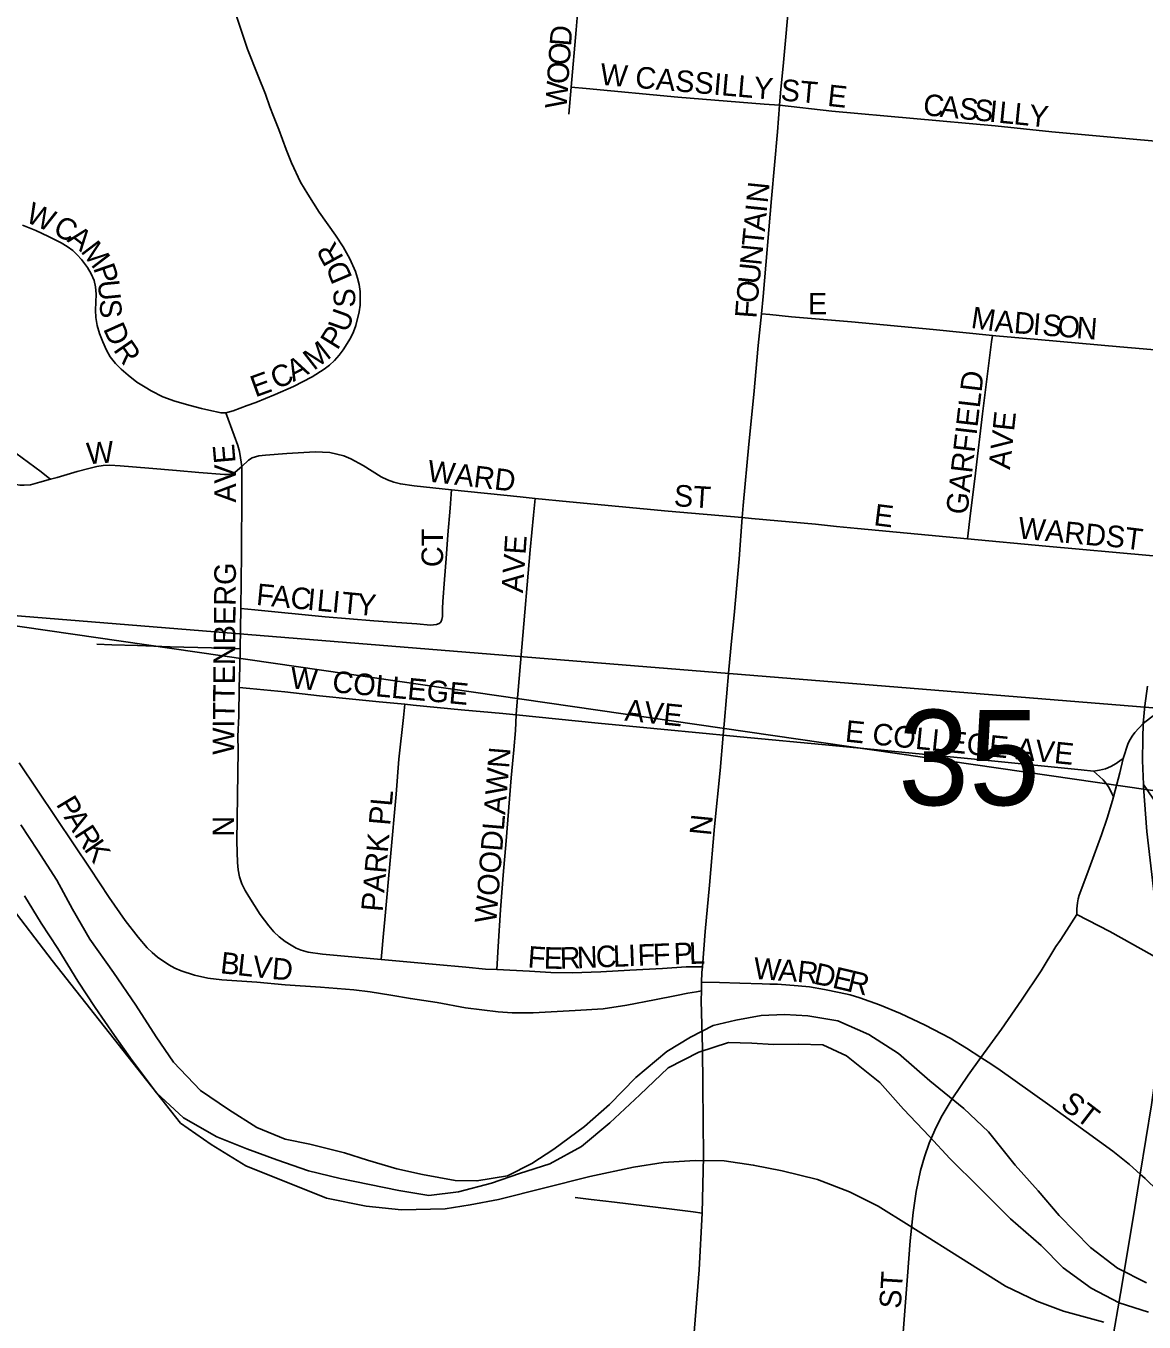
# Model space of a CAD drawing. Extents: x -209 to 4852, y 0 to 905.
# Drawn here: x 111.69 to 121.5, y 279.25 to 290.63 of the extents above; entities that cross this region are included whole.
import ezdxf

# ---------------------------------------------------------------- set-up
doc = ezdxf.new("R2010")
doc.units = 0
for name, color, linetype in [('GM_X_Airport_Location_Class_2', 7, 'Continuous'), ('GM_X_Airport_Location_Class_3', 7, 'Continuous'), ('GM_X_County_Subdivision_Text', 7, 'Continuous'), ('GM_X_Major_Lake', 7, 'Continuous'), ('GM_X_Rail_Line', 7, 'Continuous'), ('GM_X_Township_Road_Text', 7, 'Continuous'), ('GM_X_US_Route', 7, 'Continuous'), ('SH_Text', 7, 'Continuous')]:
    doc.layers.add(name, color=color, linetype=linetype)

msp = doc.modelspace()

# ---------------------------------------------------------------- linework, layer by layer
at = {"layer": 'GM_X_Airport_Location_Class_2'}
for points in [[(116.475, 290.093), (116.519, 290.597), (116.538, 290.842), (116.594, 291.457), (116.623, 291.758)], [(118.303, 289.934), (118.311, 290.043), (118.336, 290.308), (118.391, 290.894), (118.434, 291.377), (118.453, 291.587)], [(113.908, 289.721), (113.862, 289.837), (113.829, 289.921), (113.792, 290.03), (113.724, 290.198), (113.635, 290.426), (113.554, 290.662), (113.497, 290.841), (113.479, 290.901), (113.466, 290.961), (113.459, 291.023), (113.461, 291.086), (113.469, 291.147), (113.483, 291.207), (113.503, 291.265), (113.555, 291.401)], [(116.454, 289.856), (116.475, 290.093)], [(116.475, 290.093), (116.605, 290.081), (117.41, 290.004), (118.168, 289.944), (118.303, 289.934)], [(118.143, 288.103), (118.158, 288.254), (118.233, 289.116), (118.285, 289.702), (118.303, 289.934)], [(118.303, 289.934), (118.761, 289.883), (120.194, 289.752), (120.692, 289.702), (121.437, 289.634), (121.735, 289.606), (121.982, 289.582), (122.096, 289.57)], [(113.444, 287.233), (113.509, 287.252), (113.569, 287.274), (113.631, 287.297), (113.708, 287.325), (113.877, 287.394), (114.038, 287.466), (114.202, 287.55), (114.305, 287.616), (114.353, 287.653), (114.397, 287.694), (114.437, 287.739), (114.473, 287.787), (114.537, 287.89), (114.564, 287.944), (114.585, 288.001), (114.614, 288.119), (114.621, 288.178), (114.623, 288.239), (114.621, 288.299), (114.614, 288.359), (114.6, 288.417), (114.58, 288.474), (114.531, 288.585), (114.473, 288.692), (114.406, 288.793), (114.262, 288.994), (114.162, 289.152), (114.1, 289.26), (114.02, 289.429), (113.974, 289.545), (113.908, 289.721)], [(113.444, 287.233), (113.401, 287.234), (113.375, 287.239), (113.322, 287.25), (113.229, 287.272), (113.131, 287.298), (112.996, 287.336), (112.89, 287.375), (112.789, 287.426), (112.735, 287.459), (112.664, 287.503), (112.586, 287.565), (112.524, 287.617), (112.475, 287.666), (112.43, 287.725), (112.396, 287.784), (112.363, 287.856), (112.335, 287.931), (112.314, 288), (112.303, 288.072), (112.301, 288.135), (112.303, 288.206), (112.306, 288.274), (112.301, 288.339), (112.287, 288.395), (112.262, 288.454), (112.23, 288.51), (112.178, 288.581), (112.139, 288.622), (112.1, 288.66), (112.052, 288.695), (111.998, 288.726), (111.888, 288.783), (111.775, 288.834), (111.717, 288.859), (111.659, 288.881)], [(117.974, 286.314), (117.982, 286.42), (118.034, 286.958), (118.078, 287.396), (118.116, 287.825), (118.143, 288.103)], [(118.143, 288.103), (118.217, 288.096), (118.408, 288.077), (118.935, 288.033), (119.65, 287.965), (120.17, 287.913)], [(119.953, 286.127), (119.959, 286.176), (119.973, 286.302), (120.023, 286.705), (120.084, 287.225), (120.162, 287.856), (120.17, 287.913)], [(120.17, 287.913), (120.199, 287.91), (120.569, 287.877), (121.288, 287.814), (121.662, 287.781), (121.839, 287.759), (121.921, 287.742)], [(113.584, 286.763), (113.573, 286.839), (113.563, 286.893), (113.549, 286.946), (113.517, 287.036), (113.444, 287.233)], [(110.972, 286.988), (111.28, 286.787), (111.384, 286.718), (111.547, 286.626), (111.605, 286.604), (111.636, 286.599), (111.674, 286.598), (111.73, 286.603), (111.811, 286.624), (111.906, 286.65)], [(111.601, 286.88), (111.711, 286.797), (111.822, 286.717), (111.885, 286.667), (111.906, 286.65)], [(113.584, 286.763), (113.643, 286.819), (113.676, 286.84), (113.732, 286.855), (113.791, 286.863), (113.978, 286.877), (114.228, 286.89), (114.291, 286.889), (114.355, 286.884), (114.418, 286.872), (114.479, 286.855), (114.539, 286.831), (114.65, 286.771), (114.808, 286.672), (114.862, 286.645), (114.917, 286.624), (114.976, 286.609), (115.097, 286.592), (115.425, 286.558)], [(111.906, 286.65), (111.963, 286.666), (112.14, 286.719), (112.242, 286.746), (112.311, 286.762), (112.366, 286.77), (112.427, 286.773), (112.517, 286.769), (112.768, 286.749), (113.012, 286.727), (113.206, 286.709), (113.431, 286.693), (113.468, 286.693), (113.501, 286.7), (113.526, 286.713), (113.584, 286.763)], [(113.574, 285.515), (113.582, 285.995), (113.585, 286.553), (113.584, 286.763)], [(113.574, 285.515), (113.697, 285.503), (114.314, 285.444), (114.741, 285.409), (114.945, 285.394), (115.119, 285.381), (115.239, 285.371), (115.292, 285.375), (115.315, 285.383), (115.33, 285.396), (115.339, 285.418), (115.344, 285.445), (115.344, 285.515), (115.348, 285.576), (115.363, 285.771), (115.377, 285.956), (115.392, 286.163), (115.413, 286.398), (115.422, 286.521), (115.425, 286.558)], [(115.425, 286.558), (116.026, 286.497), (116.157, 286.483)], [(115.991, 284.582), (115.995, 284.626), (116.041, 285.177), (116.114, 286.03), (116.143, 286.336), (116.157, 286.483)], [(116.157, 286.483), (116.459, 286.451), (117.324, 286.371), (117.974, 286.314)], [(117.808, 284.403), (117.816, 284.499), (117.857, 284.98), (117.882, 285.23), (117.903, 285.458), (117.948, 285.953), (117.974, 286.314)], [(117.974, 286.314), (118.057, 286.307), (118.618, 286.256), (118.803, 286.237), (118.987, 286.218), (119.953, 286.127)], [(119.953, 286.127), (120.638, 286.062), (121.548, 285.981), (121.715, 285.966)], [(113.569, 285.162), (113.574, 285.515)], [(112.313, 285.202), (112.442, 285.197), (112.669, 285.191), (112.954, 285.18), (113.318, 285.17), (113.44, 285.166), (113.569, 285.162)], [(113.562, 284.823), (113.566, 285.003), (113.569, 285.162)], [(113.964, 282.593), (113.912, 282.633), (113.865, 282.678), (113.822, 282.729), (113.745, 282.829), (113.644, 282.987), (113.612, 283.041), (113.584, 283.099), (113.564, 283.159), (113.552, 283.222), (113.545, 283.285), (113.541, 283.469), (113.551, 284.272), (113.55, 284.392), (113.557, 284.575), (113.562, 284.823)], [(113.562, 284.823), (113.655, 284.814), (113.96, 284.783), (114.265, 284.75), (114.556, 284.719), (114.79, 284.697), (115.015, 284.675)], [(114.806, 282.435), (114.809, 282.468), (114.828, 282.664), (114.84, 282.785), (114.937, 283.886), (114.963, 284.192), (115.002, 284.559), (115.015, 284.675)], [(115.015, 284.675), (115.087, 284.668), (115.51, 284.627), (115.873, 284.594), (115.991, 284.582)], [(121.494, 284.506), (121.633, 284.614), (121.649, 284.626), (121.66, 284.633), (121.682, 284.642), (121.706, 284.649), (121.742, 284.657), (121.794, 284.664), (121.883, 284.671)], [(115.821, 282.346), (115.833, 282.549), (115.855, 282.871), (115.877, 283.176), (115.903, 283.475), (115.948, 284.029), (115.972, 284.276), (115.985, 284.444), (115.991, 284.582)], [(115.991, 284.582), (116.71, 284.509), (117.687, 284.415), (117.808, 284.403)], [(121.317, 284.198), (121.362, 284.334), (121.379, 284.365), (121.398, 284.394), (121.421, 284.427), (121.494, 284.506)], [(117.625, 282.37), (117.65, 282.681), (117.687, 283.088), (117.732, 283.603), (117.78, 284.095), (117.808, 284.403)], [(117.808, 284.403), (117.958, 284.39), (118.767, 284.313), (120.075, 284.188), (120.948, 284.101), (121.056, 284.088)], [(111.631, 284.162), (112.112, 283.441), (112.25, 283.236), (112.421, 282.98), (112.561, 282.776), (112.673, 282.63), (112.753, 282.538), (112.797, 282.495), (112.843, 282.456), (112.943, 282.387), (112.996, 282.359), (113.052, 282.336), (113.168, 282.298), (113.287, 282.271), (113.408, 282.257), (113.717, 282.235), (113.965, 282.213), (114.274, 282.191), (114.568, 282.167), (114.711, 282.15), (114.89, 282.121), (115.063, 282.092), (115.298, 282.056), (115.546, 282.011), (115.833, 281.975), (115.956, 281.967), (116.14, 281.967), (116.51, 281.987), (116.754, 282.002), (116.962, 282.033), (117.206, 282.081), (117.397, 282.117), (117.499, 282.14), (117.574, 282.152), (117.617, 282.159)], [(121.056, 284.088), (121.111, 284.097), (121.162, 284.108), (121.211, 284.128), (121.255, 284.154), (121.3, 284.186), (121.317, 284.198)], [(121.233, 283.862), (121.289, 284.074), (121.317, 284.198)], [(121.056, 284.088), (121.111, 284.04), (121.142, 284.011), (121.171, 283.978), (121.196, 283.942), (121.219, 283.892), (121.233, 283.862)], [(120.911, 282.829), (120.912, 282.88), (120.916, 282.933), (120.924, 282.968), (120.932, 282.999), (120.999, 283.177), (121.128, 283.528), (121.178, 283.676), (121.224, 283.829), (121.233, 283.862)], [(120.07, 281.575), (120.249, 281.822), (120.426, 282.076), (120.597, 282.336), (120.728, 282.548), (120.764, 282.6), (120.797, 282.65), (120.911, 282.829)], [(120.911, 282.829), (121.201, 282.681), (121.571, 282.472), (121.637, 282.435), (121.73, 282.383), (121.839, 282.331), (121.892, 282.307)], [(113.964, 282.593), (114.017, 282.559), (114.061, 282.534), (114.105, 282.515), (114.167, 282.499), (114.292, 282.48), (114.806, 282.435)], [(114.806, 282.435), (115.289, 282.392), (115.55, 282.367), (115.721, 282.35), (115.821, 282.346)], [(115.821, 282.346), (116.108, 282.332), (116.296, 282.321), (116.484, 282.317), (116.733, 282.325), (116.989, 282.341), (117.274, 282.356), (117.484, 282.37), (117.578, 282.37), (117.625, 282.37)], [(117.619, 282.236), (117.62, 282.319), (117.625, 282.37)], [(117.617, 282.159), (117.619, 282.236)], [(117.619, 282.236), (117.776, 282.232), (117.954, 282.228), (118.151, 282.22), (118.218, 282.219), (118.284, 282.218), (118.465, 282.204), (118.565, 282.195), (118.698, 282.17), (118.825, 282.146), (118.922, 282.123), (119.007, 282.099), (119.18, 282.036), (119.363, 281.959), (119.58, 281.859), (119.8, 281.743), (119.944, 281.657), (120.07, 281.575)], [(117.624, 280.208), (117.635, 280.705), (117.63, 281.326), (117.626, 281.656), (117.615, 282.071), (117.617, 282.159)], [(119.333, 278.432), (119.388, 279.159), (119.425, 279.655), (119.449, 279.965), (119.474, 280.213), (119.501, 280.399), (119.54, 280.582), (119.574, 280.703), (119.616, 280.821), (119.665, 280.937), (119.721, 281.049), (119.817, 281.211), (119.957, 281.418), (120.07, 281.575)], [(120.07, 281.575), (120.134, 281.533), (120.219, 281.477), (120.674, 281.153), (121.226, 280.753), (121.373, 280.636), (121.468, 280.551), (121.512, 280.512), (121.733, 280.296), (121.92, 280.134), (121.968, 280.097), (122.018, 280.065), (122.072, 280.038), (122.128, 280.016), (122.186, 279.999), (122.245, 279.988), (122.367, 279.976), (122.614, 279.976), (123.482, 279.995), (124.722, 279.991), (125.961, 280.011), (126.21, 280.012), (126.335, 280.012)], [(116.508, 280.345), (116.649, 280.328), (116.854, 280.303), (117.118, 280.271), (117.358, 280.242), (117.544, 280.22), (117.624, 280.208)], [(117.516, 278.585), (117.521, 278.74), (117.532, 278.906), (117.597, 279.711), (117.624, 280.208)]]:
    msp.add_lwpolyline(points, dxfattribs=at)
at = {"layer": 'GM_X_County_Subdivision_Text'}
msp.add_lwpolyline([(121.193, 278.887), (121.211, 279.013), (121.306, 279.569), (121.42, 280.257), (121.468, 280.551), (121.566, 281.158), (121.615, 281.519), (121.636, 281.77), (121.648, 282.006), (121.646, 282.262), (121.637, 282.435), (121.634, 282.503), (121.613, 282.803), (121.525, 283.557), (121.496, 283.946), (121.495, 283.972), (121.487, 284.182), (121.489, 284.374), (121.494, 284.506), (121.509, 284.662), (121.532, 284.835)], dxfattribs=at)
at = {"layer": 'GM_X_Major_Lake'}
for points in [[(111.645, 283.617), (111.792, 283.393), (111.96, 283.13), (112.098, 282.876), (112.251, 282.614), (112.457, 282.321), (112.655, 282.035), (112.831, 281.757), (112.985, 281.533), (113.222, 281.284), (113.468, 281.119), (113.715, 280.961), (113.963, 280.856)], [(116.813, 281.001), (116.565, 280.794), (116.288, 280.641), (116.02, 280.557), (115.775, 280.471), (115.485, 280.395), (115.226, 280.363), (114.962, 280.407), (114.448, 280.511), (114.169, 280.578), (113.89, 280.676), (113.627, 280.773), (113.364, 280.878), (113.072, 281.045), (112.834, 281.263), (112.621, 281.549), (112.466, 281.766), (112.298, 282.013), (112.144, 282.245), (111.969, 282.53), (111.822, 282.754), (111.676, 282.993)], [(113.963, 280.856), (114.182, 280.813), (114.484, 280.738), (114.687, 280.672), (114.943, 280.597), (115.17, 280.546), (115.457, 280.494), (115.647, 280.49), (115.914, 280.536), (116.129, 280.645), (116.321, 280.77), (116.592, 280.969), (116.809, 281.161), (117.042, 281.399), (117.314, 281.628), (117.521, 281.752), (117.721, 281.854), (117.92, 281.902), (118.141, 281.942), (118.346, 281.953), (118.551, 281.94), (118.815, 281.896), (119.086, 281.775), (119.347, 281.61), (119.622, 281.368), (119.92, 281.125), (120.136, 280.922), (120.371, 280.628), (120.571, 280.403), (120.756, 280.186), (121.03, 279.905), (121.268, 279.725), (121.523, 279.597)], [(121.54, 279.339), (121.284, 279.421), (121.036, 279.548), (120.79, 279.729), (120.598, 279.923), (120.33, 280.158), (120.056, 280.43), (119.796, 280.687), (119.618, 280.881), (119.389, 281.122), (119.182, 281.355), (118.891, 281.59), (118.681, 281.686), (118.469, 281.691), (118.249, 281.689), (118.059, 281.701), (117.854, 281.706), (117.594, 281.621), (117.325, 281.483), (117.077, 281.246), (116.813, 281.001)]]:
    msp.add_lwpolyline(points, dxfattribs=at)
at = {"layer": 'GM_X_Rail_Line'}
msp.add_lwpolyline([(121.892, 282.307), (122.017, 282.488), (122.093, 282.588), (122.125, 282.64), (122.153, 282.695), (122.173, 282.752), (122.186, 282.811), (122.192, 282.868), (122.188, 282.932), (122.177, 282.992), (122.159, 283.05), (122.133, 283.105), (122.102, 283.158), (122.029, 283.259), (121.791, 283.553), (121.711, 283.653), (121.577, 283.85), (121.495, 283.972)], dxfattribs=at)
at = {"layer": 'GM_X_US_Route'}
for points in [[(119.439, 280.099), (119.168, 280.269), (118.915, 280.396), (118.635, 280.504), (118.326, 280.579), (118.072, 280.63), (117.817, 280.668), (117.562, 280.669), (117.282, 280.653), (117.02, 280.611), (116.638, 280.529), (115.835, 280.328), (115.589, 280.281), (115.369, 280.247), (114.984, 280.236), (114.676, 280.269), (114.326, 280.34), (113.62, 280.622), (113.314, 280.81), (113.047, 280.999), (111.921, 282.425), (111.531, 282.934)], [(121.148, 279.251), (120.795, 279.348), (120.561, 279.434), (120.284, 279.566), (119.969, 279.765), (119.439, 280.099)]]:
    msp.add_lwpolyline(points, dxfattribs=at)
at = {"layer": 'SH_Text'}
msp.add_lwpolyline([(110.173, 285.569), (202.362, 278.085), (232.041, 278.085), (232.041, 272.446), (202.369, 272.22)], close=True, dxfattribs=at)

# ---------------------------------------------------------------- texts
at = {"layer": 'GM_X_Airport_Location_Class_3'}
for s, height, rotation, p in [('D', 0.189, 85.4052, (116.472, 290.447)), ('O', 0.189, 85.8879, (116.46, 290.281)), ('O', 0.189, 85.8879, (116.448, 290.115)), ('W CASSILLY ST', 0.18939, 355.0038, (116.722, 290.115)), ('W', 0.189, 85.894, (116.433, 289.899)), ('E', 0.189, 353.7651, (118.717, 289.929)), ('C', 0.189, 354.2338, (119.556, 289.848)), ('A', 0.189, 354.2478, (119.705, 289.833)), ('S', 0.189, 354.2269, (119.871, 289.816)), ('S', 0.189, 354.2369, (120.003, 289.803)), ('I', 0.189, 354.2462, (120.136, 289.79)), ('L', 0.189, 354.2615, (120.219, 289.781)), ('L', 0.189, 354.2269, (120.352, 289.768)), ('Y', 0.189, 354.2478, (120.484, 289.754)), ('N', 0.189, 84.2253, (118.198, 289.07)), ('W', 0.189, 336.5873, (111.676, 288.915)), ('I', 0.189, 84.1763, (118.189, 288.987)), ('C', 0.189, 332.4575, (111.916, 288.809)), ('A', 0.189, 84.2253, (118.173, 288.821)), ('A', 0.189, 322.2381, (112.042, 288.744)), ('T', 0.189, 84.2223, (118.159, 288.688)), ('M', 0.189, 307.3654, (112.164, 288.651)), ('R', 0.189, 118.8754, (114.482, 288.593)), ('N', 0.189, 84.2253, (118.142, 288.522)), ('P', 0.189, 288.9535, (112.278, 288.506)), ('D', 0.189, 113.1257, (114.557, 288.421)), ('U', 0.189, 84.2198, (118.126, 288.357)), ('U', 0.189, 275.5823, (112.319, 288.392)), ('O', 0.189, 84.3307, (118.109, 288.191)), ('S', 0.189, 90.7483, (114.58, 288.159)), ('E', 0.189, 0, (118.552, 288.098)), ('S', 0.189, 273.1435, (112.335, 288.228)), ('U', 0.189, 70.3537, (114.512, 287.93)), ('F', 0.189, 85.7061, (118.099, 288.059)), ('M', 0.189, 351.2594, (119.975, 287.981)), ('A', 0.189, 354.778, (120.185, 287.949)), ('D', 0.189, 355.4431, (120.354, 287.934)), ('D', 0.189, 294.0876, (112.364, 287.972)), ('I', 0.189, 355.4505, (120.52, 287.921)), ('S', 0.189, 355.4694, (120.603, 287.914)), ('O', 0.189, 355.4705, (120.736, 287.904)), ('N', 0.189, 355.4487, (120.902, 287.89)), ('P', 0.189, 58.1471, (114.422, 287.777)), ('R', 0.189, 304.5297, (112.451, 287.787)), ('M', 0.189, 37.905, (114.216, 287.6)), ('C', 0.189, 24.0359, (113.888, 287.437)), ('A', 0.189, 27.1644, (114.035, 287.503)), ('E', 0.189, 19.9644, (113.702, 287.368)), ('GARFIELD', 0.1894, 83.387, (119.95, 286.334)), ('AVE', 0.1894, 83.8801, (120.324, 286.732)), ('W', 0.189, 4.4941, (112.228, 286.781)), ('E', 0.189, 95.0445, (113.53, 286.797)), ('V', 0.189, 90.387, (113.532, 286.613)), ('WARD', 0.1894, 353.2096, (115.206, 286.632)), ('A', 0.189, 90.3935, (113.533, 286.446)), ('ST', 0.1894, 356.4254, (117.371, 286.415)), ('E', 0.189, 352.8783, (119.123, 286.248)), ('WARD', 0.1894, 354.5626, (120.389, 286.132)), ('CT', 0.1894, 90, (115.35, 285.879)), ('ST', 0.1894, 352.8649, (121.156, 286.065)), ('AVE', 0.1894, 86.0574, (116.05, 285.649)), ('WITTENBERG', 0.1894, 89.4212, (113.516, 284.23)), ('F', 0.189, 354.5014, (113.705, 285.548)), ('A', 0.189, 354.5189, (113.838, 285.535)), ('C', 0.189, 354.5021, (114.004, 285.52)), ('I', 0.189, 354.4851, (114.153, 285.505)), ('L', 0.189, 354.5167, (114.236, 285.497)), ('I', 0.189, 354.4851, (114.369, 285.484)), ('T', 0.189, 354.5167, (114.452, 285.476)), ('Y', 0.189, 355.094, (114.587, 285.463)), ('W', 0.189, 355.6039, (114.005, 284.815)), ('COLLEGE', 0.1894, 354.5575, (114.372, 284.782)), ('AVE', 0.1894, 354.0977, (116.939, 284.532)), ('E COLLEGE AVE', 0.18939, 354.1297, (118.872, 284.348)), ('WOODLAWN', 0.1894, 85.2929, (115.816, 282.748)), ('PARK PL', 0.1894, 84.9857, (114.819, 282.849)), ('P', 0.189, 301.0294, (111.949, 283.798)), ('A', 0.189, 301.0162, (112.018, 283.684)), ('N', 0.189, 84.2916, (117.7, 283.516)), ('R', 0.189, 302.7739, (112.107, 283.535)), ('N', 0.189, 90, (113.516, 283.513)), ('K', 0.189, 304.9239, (112.193, 283.403)), ('F', 0.189, 355.8171, (116.088, 282.365)), ('E', 0.189, 358.7265, (116.232, 282.355)), ('R', 0.189, 2.048, (116.377, 282.352)), ('N', 0.189, 2.2249, (116.527, 282.357)), ('C', 0.189, 2.1858, (116.694, 282.364)), ('L', 0.189, 2.2153, (116.844, 282.369)), ('I', 0.189, 2.2295, (116.977, 282.375)), ('F', 0.189, 2.1858, (117.06, 282.378)), ('F', 0.189, 2.2153, (117.194, 282.383)), ('P', 0.189, 2.2153, (117.377, 282.39)), ('L', 0.189, 1.3932, (117.51, 282.395)), ('B', 0.189, 353.6249, (113.389, 282.315)), ('L', 0.189, 353.6387, (113.539, 282.298)), ('V', 0.189, 353.626, (113.671, 282.283)), ('D', 0.189, 355.0183, (113.842, 282.264)), ('W', 0.189, 356.0965, (118.071, 282.265)), ('A', 0.189, 356.0841, (118.287, 282.25)), ('R', 0.189, 353.6732, (118.451, 282.239)), ('D', 0.189, 347.9358, (118.595, 282.223)), ('E', 0.189, 346.8518, (118.757, 282.189)), ('R', 0.189, 346.8798, (118.887, 282.158)), ('ST', 0.1894, 322.4371, (120.757, 281.141)), ('ST', 0.1894, 86.4254, (119.366, 279.365))]:
    msp.add_text(s, height=height, rotation=rotation, dxfattribs=at).set_placement(p)
at = {"layer": 'GM_X_Township_Road_Text'}
msp.add_text('35', height=0.8371, rotation=0, dxfattribs=at).set_placement((119.343, 283.789))

doc.saveas('drawing.dxf')
